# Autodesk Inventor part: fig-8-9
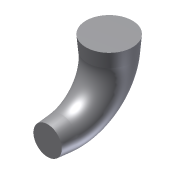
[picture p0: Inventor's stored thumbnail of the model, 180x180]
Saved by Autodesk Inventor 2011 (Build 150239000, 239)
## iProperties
Shininess: 77.0
Length Units: 11269
Angle Units: 11279
Time Units: 11290
Mass Units: 11283
Length Display Precision: 3
Angle Display Precision: 2
Created: 2001-12
Part Number: fig-8-9
Document SubType Name: Modeling
Designer: CADSoft
Density: 1 g/cm^3
Density: 0.0
Volumn: 0.0
Area: 0.0
PropertySet Name: Model Information
Control State: 0
Master: False
Checked Out: False
Author: CADSoft
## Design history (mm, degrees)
sketch "Sketch6"
  geometry: L1 (-48.928, -34.062)-(-33.928, -34.062); L2 (16.072, 15.938)-(16.072, 30.938); A1 r 50 centre (-33.928, 15.938) between (-33.928, -34.062) and (16.072, 15.938)
  constraints: 4 end point, 2 point on circle, 2 tangent, 1 centre point, 1 horizontal, 1 perpendicular
  dimensions: "d4" = 15 distance of L1.start L1.end; "d5" = 15 distance of L2.start L2.end; "d6" = 50 radius of A1
workplane "Work Plane1"
sketch "Sketch7"
  geometry: C1 r 15 at (0, 0)
  constraints: 1 centre point
  dimensions: "d7" = 30 diameter of C1
sweep "Sweep7" sketch "Sketch7" dims "d13" = 5 deg
body "Solid1"
